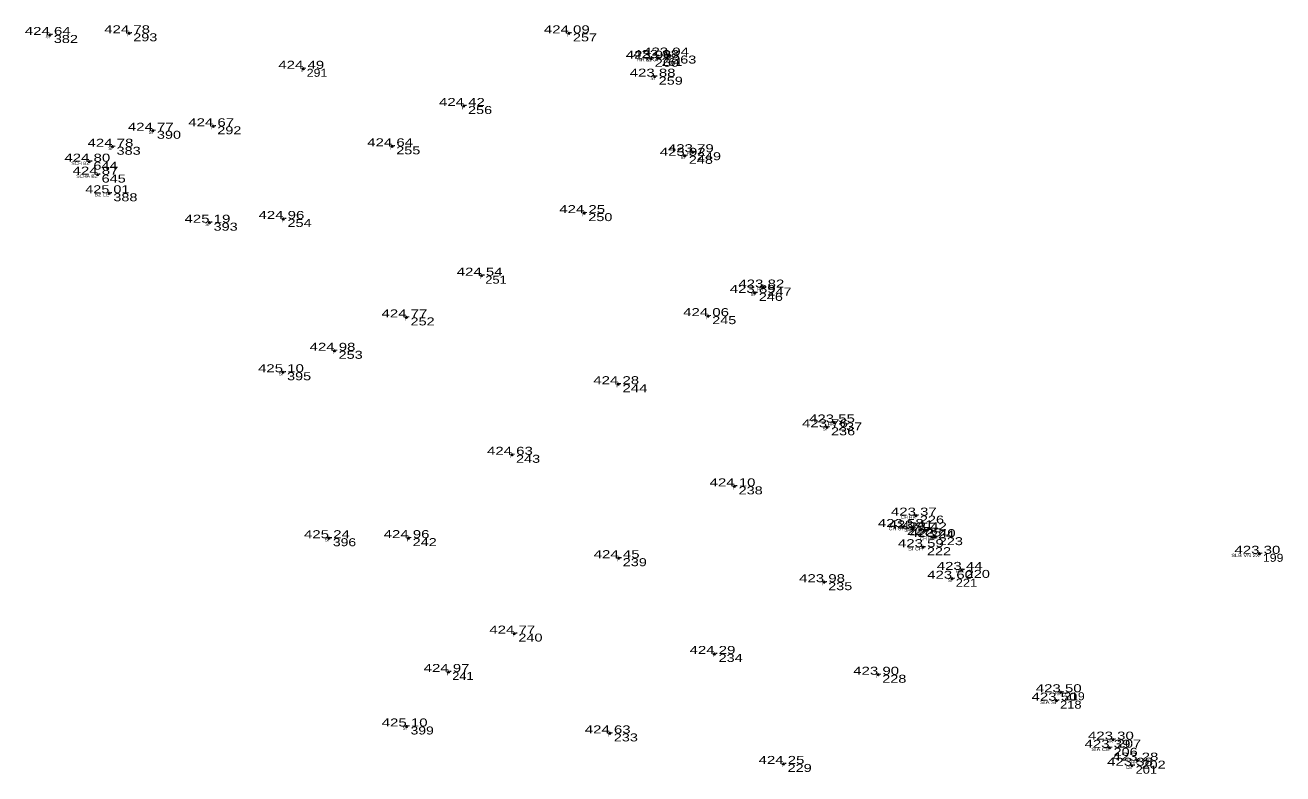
# Model space of a CAD drawing. Extents: x -639373 to -639056, y -1138651 to -1138359.
# Drawn here: x -639312.1 to -639194.2, y -1138500.1 to -1138429.9 of the extents above; entities that cross this region are included whole.
import ezdxf
from ezdxf.enums import TextEntityAlignment as Align

# ---------------------------------------------------------------- set-up
doc = ezdxf.new("R2010")
doc.units = 0
doc.header["$LTSCALE"] = 0.3
doc.header["$PDMODE"] = 32
doc.header["$PDSIZE"] = 0.15
for name, color, linetype in [('11', 7, 'Continuous'), ('12', 7, 'Continuous'), ('13', 7, 'Continuous'), ('14', 7, 'Continuous'), ('57', 7, 'Continuous')]:
    doc.layers.add(name, color=color, linetype=linetype)

msp = doc.modelspace()

# ---------------------------------------------------------------- linework, layer by layer
at = {"layer": '11'}
for p in [(-639309.8, -1138430.87), (-639302.36, -1138430.71), (-639261.15, -1138430.72), (-639253.48, -1138433.1), (-639252.78, -1138433.03), (-639251.85, -1138432.8), (-639286.04, -1138434.04), (-639253.11, -1138434.78), (-639270.98, -1138437.53), (-639300.14, -1138439.85), (-639294.48, -1138439.43), (-639303.92, -1138441.35), (-639277.71, -1138441.31), (-639306.09, -1138442.75), (-639250.29, -1138442.2), (-639249.53, -1138441.86), (-639305.32, -1138443.96), (-639304.22, -1138445.71), (-639259.71, -1138447.57), (-639294.83, -1138448.47), (-639287.9, -1138448.12), (-639269.32, -1138453.44), (-639242.92, -1138454.55), (-639243.73, -1138455.05), (-639276.37, -1138457.35), (-639248.1, -1138457.23), (-639283.11, -1138460.48), (-639287.94, -1138462.49), (-639256.52, -1138463.61), (-639236.3, -1138467.2), (-639236.96, -1138467.65), (-639266.48, -1138470.23), (-639245.62, -1138473.19), (-639229.85, -1138477), (-639228.63, -1138475.93), (-639283.63, -1138478.05), (-639276.17, -1138478.04), (-639228.89, -1138477.13), (-639227.68, -1138477.31), (-639226.86, -1138477.95), (-639227.97, -1138478.89), (-639256.48, -1138479.92), (-639196.43, -1138479.51), (-639224.33, -1138481.02), (-639237.23, -1138482.17), (-639225.23, -1138481.85), (-639266.26, -1138486.99), (-639247.5, -1138488.9), (-639272.42, -1138490.59), (-639232.16, -1138490.85), (-639215.45, -1138493.28), (-639215.05, -1138492.49), (-639276.35, -1138495.7), (-639257.32, -1138496.35), (-639210.16, -1138496.93), (-639210.48, -1138497.7), (-639241.03, -1138499.21), (-639208.37, -1138499.38), (-639207.86, -1138498.9)]:
    msp.add_point(p, dxfattribs=at)

# ---------------------------------------------------------------- texts
at = {"layer": '12'}
for s, width, p in [('424.64 ', 1.4, (-639309.8, -1138430.87)), ('423.94 ', 1.4, (-639251.85, -1138432.8)), ('423.98 ', 1.4, (-639252.78, -1138433.03)), ('424.77 ', 1.4, (-639300.14, -1138439.85)), ('424.78 ', 1.4, (-639303.92, -1138441.35)), ('423.79 ', 1.4, (-639249.53, -1138441.86)), ('424.80 ', 1.4, (-639306.09, -1138442.75)), ('424.87 ', 1.4, (-639305.32, -1138443.96)), ('425.01 ', 1.35, (-639304.219, -1138445.71)), ('425.19 ', 1.4, (-639294.83, -1138448.47)), ('423.82 ', 1.4, (-639242.92, -1138454.55)), ('423.55 ', 1.4, (-639236.3, -1138467.2)), ('423.37 ', 1.4, (-639228.63, -1138475.93)), ('423.58 ', 1.4, (-639229.85, -1138477)), ('423.40 ', 1.4, (-639226.86, -1138477.95)), ('423.30 ', 1.4, (-639196.43, -1138479.51)), ('423.44 ', 1.4, (-639224.33, -1138481.02)), ('423.50 ', 1.4, (-639215.05, -1138492.49)), ('423.30 ', 1.4, (-639210.16, -1138496.93))]:
    msp.add_text(s, height=0.75, dxfattribs=dict(at, width=width)).set_placement(p, align=Align.CENTER)
at = {"layer": '13'}
for s, width, p in [(' 382', 1.35, (-639309.8, -1138431.62)), (' 293', 1.35, (-639302.36, -1138431.46)), (' 257', 1.35, (-639261.15, -1138431.47)), (' 260', 1.35, (-639253.48, -1138433.85)), (' 261', 1.15, (-639252.78, -1138433.78)), (' 263', 1.35, (-639251.85, -1138433.55)), (' 291', 1.15, (-639286.04, -1138434.79)), (' 259', 1.35, (-639253.11, -1138435.53)), (' 256', 1.35, (-639270.98, -1138438.28)), (' 390', 1.35, (-639300.14, -1138440.6)), (' 292', 1.35, (-639294.48, -1138440.18)), (' 383', 1.35, (-639303.92, -1138442.1)), (' 255', 1.35, (-639277.71, -1138442.06)), (' 644', 1.35, (-639306.09, -1138443.5)), (' 248', 1.35, (-639250.29, -1138442.95)), (' 249', 1.35, (-639249.53, -1138442.61)), (' 645', 1.35, (-639305.32, -1138444.71)), (' 388', 1.35, (-639304.22, -1138446.46)), (' 393', 1.35, (-639294.83, -1138449.22)), (' 254', 1.35, (-639287.9, -1138448.87)), (' 250', 1.35, (-639259.71, -1138448.32)), (' 251', 1.2, (-639269.32, -1138454.19)), (' 247', 1.35, (-639242.92, -1138455.3)), (' 246', 1.35, (-639243.73, -1138455.8)), (' 252', 1.35, (-639276.37, -1138458.1)), (' 245', 1.35, (-639248.1, -1138457.98)), (' 253', 1.35, (-639283.11, -1138461.23)), (' 395', 1.35, (-639287.94, -1138463.24)), (' 244', 1.4, (-639256.52, -1138464.36)), (' 237', 1.35, (-639236.3, -1138467.95)), (' 236', 1.35, (-639236.96, -1138468.4)), (' 243', 1.35, (-639266.48, -1138470.98)), (' 238', 1.35, (-639245.62, -1138473.94)), (' 226', 1.35, (-639228.63, -1138476.68)), (' 396', 1.3, (-639283.63, -1138478.8)), (' 242', 1.35, (-639276.17, -1138478.79)), (' 227', 1.35, (-639229.85, -1138477.75)), (' 225', 1.35, (-639228.89, -1138477.88)), (' 224', 1.35, (-639227.68, -1138478.06)), (' 223', 1.35, (-639226.86, -1138478.7)), (' 222', 1.35, (-639227.97, -1138479.64)), (' 239', 1.35, (-639256.48, -1138480.67)), (' 199', 1.15, (-639196.43, -1138480.26)), (' 220', 1.35, (-639224.33, -1138481.77)), (' 235', 1.35, (-639237.23, -1138482.92)), (' 221', 1.2, (-639225.23, -1138482.6)), (' 240', 1.35, (-639266.26, -1138487.74)), (' 234', 1.35, (-639247.5, -1138489.65)), (' 241', 1.2, (-639272.42, -1138491.34)), (' 228', 1.35, (-639232.16, -1138491.6)), (' 218', 1.2, (-639215.45, -1138494.03)), (' 219', 1.15, (-639215.05, -1138493.24)), (' 399', 1.3, (-639276.35, -1138496.45)), (' 233', 1.35, (-639257.32, -1138497.1)), (' 207', 1.35, (-639210.16, -1138497.68)), (' 206', 1.35, (-639210.48, -1138498.45)), (' 229', 1.35, (-639241.03, -1138499.96)), (' 202', 1.35, (-639207.86, -1138499.65)), (' 201', 1.2, (-639208.37, -1138500.13))]:
    msp.add_text(s, height=0.75, dxfattribs=dict(at, width=width)).set_placement(p)
at = {"layer": '14'}
for s, width, p in [('424.78 ', 1.4, (-639302.36, -1138430.71)), ('424.09 ', 1.4, (-639261.15, -1138430.72)), ('424.49 ', 1.4, (-639286.04, -1138434.04)), ('423.96 ', 1.4, (-639253.479, -1138433.1)), ('423.88 ', 1.4, (-639253.11, -1138434.78)), ('424.42 ', 1.4, (-639270.98, -1138437.53)), ('424.67 ', 1.4, (-639294.48, -1138439.43)), ('424.64 ', 1.4, (-639277.71, -1138441.31)), ('423.92 ', 1.4, (-639250.29, -1138442.2)), ('424.96 ', 1.4, (-639287.899, -1138448.12)), ('424.25 ', 1.4, (-639259.71, -1138447.57)), ('424.54 ', 1.4, (-639269.32, -1138453.44)), ('423.89 ', 1.4, (-639243.73, -1138455.05)), ('424.77 ', 1.4, (-639276.37, -1138457.35)), ('424.06 ', 1.4, (-639248.099, -1138457.23)), ('424.98 ', 1.4, (-639283.11, -1138460.48)), ('425.10 ', 1.4, (-639287.94, -1138462.49)), ('424.28 ', 1.4, (-639256.52, -1138463.61)), ('423.76 ', 1.4, (-639236.959, -1138467.65)), ('424.63 ', 1.4, (-639266.48, -1138470.23)), ('424.10 ', 1.4, (-639245.62, -1138473.19)), ('423.41 ', 1.35, (-639228.889, -1138477.13)), ('423.42 ', 1.4, (-639227.68, -1138477.31)), ('425.24 ', 1.4, (-639283.63, -1138478.05)), ('424.96 ', 1.4, (-639276.169, -1138478.04)), ('423.59 ', 1.4, (-639227.97, -1138478.89)), ('424.45 ', 1.4, (-639256.48, -1138479.92)), ('423.98 ', 1.4, (-639237.23, -1138482.17)), ('423.60 ', 1.4, (-639225.23, -1138481.85)), ('424.77 ', 1.4, (-639266.26, -1138486.99)), ('424.29 ', 1.4, (-639247.5, -1138488.9)), ('424.97 ', 1.4, (-639272.42, -1138490.59)), ('423.90 ', 1.4, (-639232.16, -1138490.85)), ('423.50 ', 1.4, (-639215.45, -1138493.28)), ('425.10 ', 1.4, (-639276.35, -1138495.7)), ('424.63 ', 1.4, (-639257.32, -1138496.35)), ('423.39 ', 1.4, (-639210.48, -1138497.7)), ('423.28 ', 1.4, (-639207.86, -1138498.9)), ('424.25 ', 1.4, (-639241.03, -1138499.21)), ('423.38 ', 1.4, (-639208.37, -1138499.38))]:
    msp.add_text(s, height=0.75, dxfattribs=dict(at, width=width)).set_placement(p, align=Align.CENTER)
at = {"layer": '57'}
for s, width, p in [('SI', 1.05, (-639309.8, -1138431.17)), ('T', 0.85, (-639302.36, -1138431.01)), ('T', 0.85, (-639261.15, -1138431.02)), ('HR K KA', 1.25, (-639252.78, -1138433.33)), ('SI', 1.05, (-639253.48, -1138433.4)), ('K', 0.65, (-639251.849, -1138433.1)), ('T', 0.85, (-639286.04, -1138434.34)), ('SI', 1.05, (-639253.11, -1138435.08)), ('T', 0.85, (-639270.98, -1138437.83)), ('SI', 1.05, (-639300.14, -1138440.15)), ('T', 0.85, (-639294.48, -1138439.73)), ('SI', 1.05, (-639303.92, -1138441.65)), ('T', 0.85, (-639277.71, -1138441.61)), ('SCH BZ', 1.15, (-639306.089, -1138443.05)), ('SI', 1.05, (-639250.29, -1138442.5)), ('HR', 0.85, (-639249.529, -1138442.16)), ('SCHA BZ', 1.15, (-639305.319, -1138444.26)), ('BZ LE', 1.25, (-639304.22, -1138446.01)), ('SI', 1.05, (-639294.83, -1138448.77)), ('T', 0.85, (-639287.9, -1138448.42)), ('T', 0.85, (-639259.71, -1138447.87)), ('T', 0.85, (-639269.32, -1138453.74)), ('HR', 0.85, (-639242.919, -1138454.85)), ('SI', 1.05, (-639243.73, -1138455.35)), ('T', 0.85, (-639276.37, -1138457.65)), ('T', 0.85, (-639248.1, -1138457.53)), ('T', 0.85, (-639283.11, -1138460.78)), ('SI', 1.05, (-639287.94, -1138462.79)), ('T', 0.85, (-639256.52, -1138463.91)), ('HR', 0.85, (-639236.299, -1138467.5)), ('SI', 1.05, (-639236.96, -1138467.95)), ('T', 0.85, (-639266.48, -1138470.53)), ('T', 0.85, (-639245.62, -1138473.49)), ('CH HR', 1.1, (-639228.629, -1138476.23)), ('SI', 1.05, (-639283.63, -1138478.35)), ('T', 0.85, (-639276.17, -1138478.34)), ('CH SI', 1.25, (-639229.85, -1138477.3)), ('CH HR', 1.1, (-639226.859, -1138478.25)), ('SI CH', 1.3, (-639227.969, -1138479.19)), ('T', 0.85, (-639256.48, -1138480.22)), ('SLB VN 2X', 1.3, (-639196.43, -1138479.81)), ('HR', 0.85, (-639224.329, -1138481.32)), ('T', 0.85, (-639237.23, -1138482.47)), ('SI', 1.05, (-639225.23, -1138482.15)), ('T', 0.85, (-639266.26, -1138487.29)), ('T', 0.85, (-639247.5, -1138489.2)), ('T', 0.85, (-639272.42, -1138490.89)), ('T', 0.85, (-639232.16, -1138491.15)), ('SIA SI', 1.35, (-639215.45, -1138493.58)), ('HR', 0.85, (-639215.049, -1138492.79)), ('SI', 1.05, (-639276.35, -1138496)), ('T', 0.85, (-639257.32, -1138496.65)), ('HR', 0.85, (-639210.159, -1138497.23)), ('SIA CE', 1.3, (-639210.48, -1138498)), ('T', 0.85, (-639241.03, -1138499.51)), ('HR', 0.85, (-639207.859, -1138499.2)), ('CE', 0.9, (-639208.37, -1138499.68))]:
    msp.add_text(s, height=0.3, dxfattribs=dict(at, width=width)).set_placement(p, align=Align.RIGHT)
for p in [(-639228.889, -1138477.43), (-639227.679, -1138477.61)]:
    msp.add_text('SAK', height=0.3, dxfattribs=at).set_placement(p, align=Align.RIGHT)

doc.saveas('drawing.dxf')
